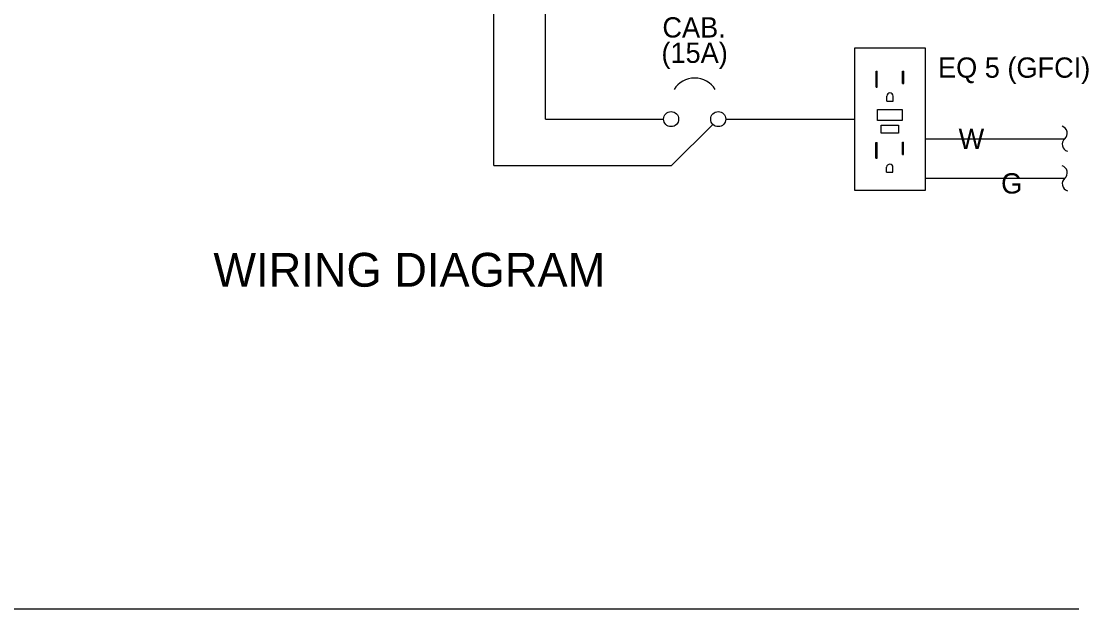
# Model space of a CAD drawing. Extents: x 99862 to 103680, y 99470 to 102076.
# Drawn here: x 100539 to 101161, y 100000 to 100347 of the extents above; entities that cross this region are included whole.
import ezdxf

# ---------------------------------------------------------------- set-up
doc = ezdxf.new("R2010")
doc.units = 0
for name, color, linetype in [('Level 1', 7, 'Continuous'), ('Level 11', 7, 'Continuous'), ('Level 20', 7, 'Continuous'), ('Level 26', 7, 'Continuous'), ('Level 40', 7, 'Continuous')]:
    doc.layers.add(name, color=color, linetype=linetype)

msp = doc.modelspace()

# ---------------------------------------------------------------- linework, layer by layer
at = {"layer": 'Level 1'}
msp.add_lwpolyline([(99862, 99999.5), (103151, 99999.5), (103151, 102075.5), (99862, 102075.5)], close=True, dxfattribs=at)
at = {"layer": 'Level 11'}
for p, q in [((101044.77, 100308.23), (101044.77, 100317.62)), ((101044.77, 100317.62), (101045.47, 100317.62)), ((101045.47, 100308.23), (101045.47, 100317.62)), ((101060.41, 100310.36), (101060.41, 100317.64)), ((101060.41, 100317.64), (101061.15, 100317.64)), ((101061.15, 100310.36), (101061.15, 100317.64)), ((101060.41, 100310.36), (101061.15, 100310.36)), ((101044.77, 100308.23), (101045.47, 100308.23)), ((101051.09, 100299.9), (101051.09, 100302.92)), ((101051.09, 100299.9), (101054.82, 100299.9)), ((101054.82, 100299.9), (101054.82, 100302.94)), ((101044.66, 100266.18), (101044.66, 100275.54)), ((101044.66, 100275.54), (101045.4, 100275.54)), ((101045.4, 100266.18), (101045.4, 100275.54)), ((101060.34, 100268.28), (101060.34, 100275.6)), ((101060.34, 100275.6), (101061.06, 100275.6)), ((101061.06, 100268.28), (101061.06, 100275.6)), ((101060.34, 100268.28), (101061.06, 100268.28)), ((101044.66, 100266.18), (101045.4, 100266.18)), ((101051, 100257.84), (101051, 100260.88)), ((101054.72, 100257.84), (101054.72, 100260.75)), ((101051, 100257.84), (101054.72, 100257.84))]:
    msp.add_line(p, q, dxfattribs=at)
for centre, start, end in [((101052.97, 100302.91), 1.14913, 179.35263), ((101052.86, 100260.77), 359.7062, 176.45807)]:
    msp.add_arc(centre, 1.86, start, end, dxfattribs=at)
at = {"layer": 'Level 26'}
for p, q in [((100849.3, 100289.33), (100849.3, 100486.06)), ((100818.77, 100261.79), (100818.77, 100430.98)), ((100849.3, 100289.33), (100919.06, 100289.33)), ((100948.23, 100286.17), (100923.85, 100261.79)), ((100955.87, 100289.33), (101031.99, 100289.33)), ((101073.96, 100277.67), (101156.33, 100277.67)), ((100818.77, 100261.79), (100923.85, 100261.79)), ((101073.96, 100254.34), (101156.33, 100254.34))]:
    msp.add_line(p, q, dxfattribs=at)
for centre in [(100923.53, 100289.33), (100951.4, 100289.33)]:
    msp.add_circle(centre, 4.47, dxfattribs=at)
for centre, radius, start, end in [((100937.46, 100299.27), 14.35, 31.81592, 148.18408), ((101153.56, 100280.93), 4.28, 310.32131, 74.28325), ((101159.1, 100274.4), 4.28, 130.32131, 254.28325), ((101153.56, 100257.61), 4.28, 310.32131, 74.28325), ((101159.1, 100251.08), 4.28, 130.32131, 254.28325)]:
    msp.add_arc(centre, radius, start, end, dxfattribs=at)
at = {"layer": 'Level 40'}
for points in [[(101031.99, 100331.29), (101031.99, 100247.37), (101073.96, 100247.37), (101073.96, 100331.29)], [(101045.64, 100295), (101060.13, 100295), (101060.13, 100288.59), (101045.64, 100288.59)], [(101047.75, 100285.75), (101058.02, 100285.75), (101058.02, 100280.92), (101047.75, 100280.92)]]:
    msp.add_lwpolyline(points, close=True, dxfattribs=at)

# ---------------------------------------------------------------- texts
at = {"layer": 'Level 20'}
for s, height, p in [('CAB.', 12, (100918.39, 100337.58)), ('(15A)', 12, (100917.82, 100322.58)), ('EQ 5 (GFCI)', 12, (101081.4, 100313.79)), ('W', 12.01, (101093.55, 100271.66)), ('G', 12.01, (101118.7, 100245.28)), ('WIRING DIAGRAM', 20, (100652.82, 100190.17))]:
    msp.add_text(s, height=height, dxfattribs=at).set_placement(p)

doc.saveas('drawing.dxf')
